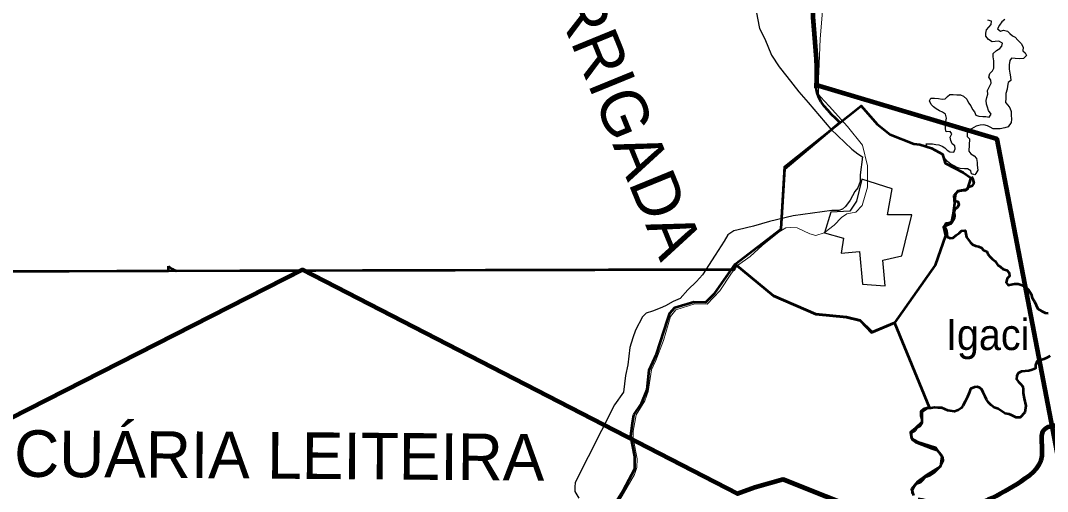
# Model space of a CAD drawing. Extents: x -1643653 to 4543381, y 1624270 to 13878484.
# Drawn here: x 746441 to 762958, y 8940067 to 8947643 of the extents above; entities that cross this region are included whole.
import ezdxf
from ezdxf.enums import TextEntityAlignment as Align

# ---------------------------------------------------------------- set-up
doc = ezdxf.new("R2010")
doc.units = 0
doc.header["$LTSCALE"] = 200
for name, color, linetype, lineweight in [('12', 7, 'Continuous', 25), ('14', 7, 'Continuous', 13), ('17', 7, 'Continuous', 53), ('21', 7, 'Continuous', 25), ('24', 7, 'Continuous', 25), ('26', 7, 'Continuous', 106), ('28', 7, 'Continuous', 53), ('60', 7, 'Continuous', 13), ('9', 7, 'Continuous', 90)]:
    doc.layers.add(name, color=color, linetype=linetype, lineweight=lineweight)
doc.layers.add('41', color=7, linetype='Continuous')
doc.layers.add('42', color=7, linetype='Continuous')

msp = doc.modelspace()

# ---------------------------------------------------------------- linework, layer by layer
at = {"layer": '12'}
for points in [[(758100.6, 8948982.2), (758153.1, 8948438), (758293, 8947683.8), (758328, 8947515.6), (758414, 8947347.3), (758520, 8947087.3), (758641.6, 8946898.6), (758763.3, 8946740.5), (758961.1, 8946495.6), (759108.2, 8946327.2), (759473.4, 8945893.6), (759814, 8945575.9), (759907.3, 8945497.2), (759983.7, 8945452)], [(759983.7, 8945452), (759944.5, 8945159.2), (759944.1, 8945052.2), (759908, 8944950.4), (759862, 8944894.4), (759785, 8944751.9), (759708.2, 8944650.2), (759662.2, 8944609.5), (759602.9, 8944588), (759488.4, 8944585.1)], [(759488.4, 8944585.1), (758867.1, 8944498.9), (758489.8, 8944407.9), (758229.7, 8944337.1), (757985, 8944276.4), (757913.6, 8944261.2), (757816.6, 8944195.2), (757760.2, 8944093.4), (757611.6, 8943869.5), (757411.8, 8943554.1), (757314.6, 8943447.3), (757171.4, 8943310), (757048.7, 8943172.7), (756936.4, 8943121.9), (756813.9, 8943055.9), (756729.6, 8943015), (756604.7, 8942969.7), (756502.7, 8942934.3), (756446.4, 8942878.3), (756333.6, 8942659.5), (756287.3, 8942537.3), (756240.8, 8942384.6), (756209.2, 8942104.5), (756173, 8941931.3), (756141.4, 8941666.5), (755992.9, 8941463), (755361.7, 8940211), (755356.3, 8940134.6), (755356.1, 8940068.4), (755421.9, 8939961.3)]]:
    msp.add_lwpolyline(points, dxfattribs=at)
at = {"layer": '12', "lineweight": 40}
msp.add_spline([(761549.2, 8957020.4), (762383.1, 8955993.9), (763257, 8954902.9), (764214.4, 8953717.3), (766168.2, 8951324.4), (767086.6, 8950171.6), (770317.8, 8946184.2), (771971, 8944146), (773006.3, 8942876.2), (773223.4, 8942642.3), (773373.7, 8942274.8), (774008.3, 8940921.5), (774359, 8940136.3), (774475.8, 8939919.1), (774642.8, 8939785.5), (774893.3, 8939668.5), (775511.2, 8939484.7), (775928.6, 8939267.5), (776078.9, 8939184), (776379.5, 8938916.7), (776680.1, 8938749.6), (776830.4, 8938582.6), (777398.1, 8938348.7), (777899.1, 8938231.7), (778550.4, 8938482.3), (779134.8, 8938866.6), (779452.1, 8939250.8), (779569, 8939384.5), (779685.9, 8939351.1), (779852.9, 8939217.4), (780086.7, 8939217.4), (780604.3, 8939451.3), (781055.2, 8939618.4), (781439.3, 8939618.4), (781823.3, 8939518.1), (782090.5, 8939401.2), (782290.9, 8939367.8), (782524.7, 8939518.1), (782858.7, 8939618.4), (783192.6, 8939651.8), (783509.9, 8939818.9), (783910.7, 8940119.6), (784278.1, 8940336.8), (784625.2, 8940434.5)], degree=3, dxfattribs=at)
at = {"layer": '14'}
for points in [[(756356.5, 8940591.2), (756296.6, 8940917.4), (756291.9, 8941034.6), (756343.8, 8941299.3), (756482.2, 8941523.2), (756533.7, 8941676), (756591, 8942022.3), (756657.8, 8942175), (756781.3, 8942495.7), (756894.8, 8942882.6), (756981.8, 8942989.4), (757287.8, 8943085.7), (757486.4, 8943080.2), (757685.9, 8943293.8), (757875.4, 8943578.7), (757972.7, 8943700.8), (758177, 8943848.1), (758371.2, 8944026.1), (758642, 8944244.6), (758749.2, 8944310.6), (758825.7, 8944315.6), (758932.7, 8944310.3), (759136.1, 8944213.1), (759232.8, 8944182.4), (759365.4, 8944228), (759528.8, 8944349.9), (759646.5, 8944477.1), (759733.3, 8944533), (759876, 8944558.2), (759978.3, 8944665), (760060.9, 8944960.3), (760062.2, 8945306.7), (759981.9, 8945637.9), (759743.6, 8945938.9), (759444.2, 8946265.5), (759307.2, 8946418.6), (759276.8, 8946459.4), (759277.1, 8946556.2), (759272.6, 8946703.9), (759283.7, 8946948.4), (759300.4, 8947350.8), (759434.4, 8948959.2)], [(756079, 8939934.6), (756314.8, 8940341.7), (756356, 8940453.7), (756356.5, 8940591.2)]]:
    msp.add_lwpolyline(points, dxfattribs=at)
at = {"layer": '17'}
msp.add_lwpolyline([(760138.8, 8942630.4), (759944.6, 8942815.9), (759724, 8942868.9), (759229.7, 8942921.8), (758550.1, 8943213.2), (757932.3, 8943725.4), (758673.7, 8944290.6), (758735.5, 8945297.2), (759962.3, 8946268.6), (760216.8, 8945977.6), (760428.7, 8945809.8), (760808.2, 8945659.7), (760905.3, 8945650.9), (761090.6, 8945589.1), (761267.1, 8945491.9), (761311.2, 8945350.6), (761602.5, 8945200.5), (761726.1, 8945112.2), (761664.3, 8944926.8), (761514.2, 8944900.3), (761452.5, 8944820.8), (761461.3, 8944697.2), (761443.6, 8944538.2), (761408.3, 8944379.3), (761284.8, 8944326.3), (761320.1, 8944185), (761152.4, 8943708.2), (760499.3, 8942781)], close=True, dxfattribs=at)
at = {"layer": '21'}
msp.add_lwpolyline([(759971.8, 8945092.7), (759884.4, 8944737), (759777.9, 8944573.9), (759473.6, 8944557.9), (759374.4, 8944228.2), (759675.4, 8944141.8), (759642.3, 8943899.6), (759934.4, 8943928.7), (759980.7, 8943402.3), (760347, 8943377.8), (760309.6, 8943788.8), (760615.6, 8943855.9), (760776.1, 8944516.6), (760383.6, 8944516.3), (760460.4, 8944936.4)], close=True, dxfattribs=at)
at = {"layer": '24'}
for points in [[(762274, 8947657.5), (762222.9, 8947622.2), (762186.9, 8947571.5), (762156, 8947510.5), (762201.5, 8947474.6), (762252.5, 8947489.6), (762313.4, 8947473.9), (762353.8, 8947432.9), (762394.3, 8947396.9), (762439.9, 8947376.3), (762480.3, 8947330.2), (762535.8, 8947273.8), (762565.9, 8947212.5), (762560.5, 8947156.5), (762600.9, 8947125.7), (762621, 8947079.7), (762569.8, 8947034.2), (762508.7, 8947029.5), (762437.6, 8947035), (762381.7, 8947040.5), (762350.9, 8946999.9), (762340.2, 8946928.7), (762339.7, 8946862.4), (762354.5, 8946796.1), (762364.3, 8946740), (762369, 8946678.9), (762328.1, 8946648.6), (762312.4, 8946587.6), (762307, 8946536.7), (762286.2, 8946470.6), (762285.7, 8946394.2), (762285.2, 8946322.8), (762320.5, 8946281.9), (762350.7, 8946240.9), (762375.7, 8946179.6), (762375.3, 8946123.6), (762380, 8946057.4), (762374.5, 8946001.4), (762328.3, 8945935.4), (762272.2, 8945915.4), (762195.8, 8945900.6), (762134.8, 8945901), (762083.9, 8945901.3), (762038.3, 8945927.1), (761992.7, 8945947.8), (761931.8, 8945963.4), (761875.8, 8945958.7), (761809.6, 8945943.9), (761738.1, 8945903.6), (761682, 8945883.6), (761666.4, 8945832.7), (761666, 8945776.7), (761706.4, 8945740.8), (761694.9, 8945542.2), (761725.1, 8945501.2), (761781.5, 8945468.3), (761814.4, 8945424.2), (761825.4, 8945358.2), (761825.4, 8945314.1), (761836.4, 8945237.1), (761803.4, 8945182), (761788.9, 8945159.5), (761738.1, 8945175.1), (761723.2, 8945226.2), (761672.6, 8945257.1), (761621.7, 8945257.4), (761555.6, 8945262.9), (761504.9, 8945278.5), (761459.3, 8945304.3), (761403.6, 8945335.2), (761347.9, 8945376.3), (761312.6, 8945417.3), (761292.5, 8945463.3), (761247.1, 8945509.4), (761176.1, 8945540.4), (761125.4, 8945561.1), (761069.6, 8945586.9), (761024, 8945607.6), (761009.1, 8945658.6), (761059.9, 8945658.3), (761110.8, 8945658), (761161.6, 8945647.5), (761212.4, 8945642.1), (761263.1, 8945621.4), (761308.7, 8945595.6), (761344.1, 8945559.7), (761389.6, 8945528.9)], [(761389.6, 8945528.9), (761450.6, 8945523.4), (761471.3, 8945579.3), (761466.6, 8945630.2), (761426.1, 8945661.1), (761401.1, 8945712.2), (761391.3, 8945768.3), (761422.1, 8945819), (761391.9, 8945859.9), (761330.8, 8945850.2), (761315.9, 8945901.2), (761316.3, 8945967.4), (761321.8, 8946018.3), (761332.3, 8946074.3), (761317.5, 8946135.5), (761272, 8946171.4), (761221.3, 8946192.1), (761165.5, 8946223.1), (761125, 8946253.9), (761089.7, 8946294.9), (761059.6, 8946351.1), (761080.2, 8946396.8), (761141.3, 8946396.4), (761207.4, 8946390.9), (761263.2, 8946380.3), (761314.1, 8946385.1), (761350, 8946420.5), (761385.8, 8946456), (761441.8, 8946455.6), (761497.7, 8946450.2), (761558.7, 8946449.8), (761609.4, 8946429.1), (761659.9, 8946377.8), (761690.1, 8946321.6), (761725.3, 8946270.4), (761750.4, 8946214.2), (761785.7, 8946173.2), (761805.7, 8946122.2), (761856.4, 8946106.6), (761917.4, 8946101.1), (761968.3, 8946100.8), (762019.1, 8946090.2), (762055, 8946135.8), (762009.7, 8946197.3), (761994.7, 8946248.3), (761974.8, 8946299.4), (761970.1, 8946355.4), (761980.6, 8946406.3), (761996.2, 8946457.1), (761991.5, 8946518.3), (762022.4, 8946574.1), (762053.3, 8946635.1), (762048.6, 8946686), (762013.3, 8946732.1), (762029, 8946793.1), (762075.1, 8946833.6), (762095.7, 8946879.3), (762096.2, 8946945.5), (762096.5, 8946996.4), (762086.8, 8947057.6), (762082.1, 8947113.7), (762138.3, 8947159.2), (762189.4, 8947194.5), (762225.3, 8947229.9), (762235.8, 8947280.8), (762175, 8947311.8), (762119, 8947307), (762068.1, 8947302.3), (762007.3, 8947338.3), (761967, 8947389.5), (761967.3, 8947440.4), (761977.9, 8947491.3), (762013.8, 8947536.9), (762049.7, 8947577.4), (762060.2, 8947633.4), (761999.3, 8947649.1)]]:
    msp.add_lwpolyline(points, dxfattribs=at)
at = {"layer": '24', "lineweight": 53}
for points in [[(761737.3, 8945134.7), (761755.2, 8945087.5), (761775.2, 8945026.3), (761739.2, 8944980.7), (761683.1, 8944955.6), (761637, 8944910), (761576, 8944905.3), (761514.8, 8944890.4), (761479, 8944855), (761468.4, 8944799), (761468, 8944743), (761518.8, 8944732.5), (761533.7, 8944681.5), (761513.1, 8944635.7), (761467.1, 8944610.6), (761451.5, 8944559.7), (761461.3, 8944508.7), (761455.9, 8944457.8), (761425, 8944407.1), (761374, 8944381.9), (761323.1, 8944377.2), (761302.4, 8944331.5), (761327.5, 8944275.3), (761337.3, 8944219.2), (761347.1, 8944163.1), (761392.7, 8944142.4), (761443.6, 8944147.2), (761489.7, 8944192.7), (761535.7, 8944223), (761576.6, 8944258.4), (761632.6, 8944263.1), (761642.4, 8944212.1), (761657.3, 8944156), (761687.5, 8944115.1), (761717.7, 8944074.1), (761753.1, 8944038.2), (761798.7, 8944017.6), (761849.5, 8944007), (761895.2, 8943986.4), (761930.5, 8943950.5), (761981.2, 8943929.8), (762001.3, 8943883.8), (762036.6, 8943842.8), (762071.9, 8943801.9), (762117.5, 8943771), (762157.7, 8943709.6), (762203.3, 8943678.8), (762243.7, 8943642.8), (762304.7, 8943627.2), (762340, 8943586.2), (762349.8, 8943530.1), (762308.8, 8943494.7), (762293.1, 8943428.6), (762323.4, 8943387.7), (762374.3, 8943397.5), (762425.2, 8943407.4), (762486.2, 8943407), (762552.2, 8943386.2), (762613, 8943350.1), (762653.4, 8943309.1), (762693.7, 8943242.6), (762713.6, 8943181.4), (762748.8, 8943125.1), (762773.8, 8943063.8), (762803.9, 8943007.6)], [(762803.9, 8943007.6), (762864.7, 8942966.5), (762920.5, 8942940.7), (762971.3, 8942935.2)], [(763002.2, 8942247.4), (762946, 8942217.2), (762900.1, 8942197.1), (762849.1, 8942177), (762787.9, 8942157.1), (762767.2, 8942101.2), (762766.8, 8942045.1), (762710.7, 8942025.1), (762659.8, 8942010.2), (762598.7, 8942000.3), (762537.6, 8941995.7), (762486.6, 8941970.5), (762465.9, 8941924.8), (762460.5, 8941873.9), (762490.7, 8941832.9), (762526.1, 8941797.1), (762561.4, 8941756.1), (762566.1, 8941705.1), (762565.7, 8941649.1)], [(762565.7, 8941649.1), (762580.6, 8941564.2), (762580.6, 8941564.2), (762611.1, 8941442.4), (762595.8, 8941335.7), (762519.6, 8941259.6), (762453.6, 8941259.6), (762377.4, 8941292.5), (762340.6, 8941308.9), (762279.2, 8941321.2), (762230.1, 8941353.9), (762164.6, 8941394.8), (762103.2, 8941419.3), (762051.3, 8941456.8), (762010.3, 8941499.8), (761975, 8941545.9), (761955, 8941597), (761924.9, 8941658.3), (761899.8, 8941709.4), (761871.3, 8941731.8), (761831, 8941748.4), (761783.1, 8941745.8), (761721.9, 8941715.6), (761696, 8941655.9), (761672.3, 8941589.5), (761634.4, 8941513.7), (761596.5, 8941447.3), (761568.1, 8941409.3), (761520.8, 8941376.1), (761463.9, 8941352.4), (761392.8, 8941366.6), (761355, 8941371.4), (761307.6, 8941390.3), (761257, 8941413), (761201, 8941413.3), (761140, 8941418.8), (761080.2, 8941404.6), (761018.6, 8941409.3), (760966.5, 8941390.3), (760919.1, 8941352.4), (760920.8, 8941343.8), (760920.4, 8941282.7), (760935.3, 8941231.7), (760934.8, 8941165.4), (760904, 8941119.8), (760852.9, 8941089.6), (760830.3, 8941047.1), (760764.8, 8941010.3), (760764.8, 8941010.3), (760764.8, 8940957.1), (760780.4, 8940901.6), (760841.2, 8940860.4), (761104.9, 8940756.8), (761184.4, 8940731.1), (761241.3, 8940660), (761269.7, 8940617.3), (761272.5, 8940557.8), (761245.1, 8940495.9), (761203.9, 8940441), (761135.3, 8940372.3), (761059.8, 8940324.2), (761025.5, 8940310.4), (760989.9, 8940299.1), (760943.7, 8940243.4), (760902.8, 8940208)], [(760902.8, 8940208), (760846.7, 8940188), (760810.8, 8940142.4), (760779.9, 8940086.5), (760779.6, 8940035.6)]]:
    msp.add_lwpolyline(points, dxfattribs=at)
at = {"layer": '26'}
msp.add_lwpolyline([(737637.3, 8917498.1), (741487, 8913799.2), (751263.9, 8913799.2), (755491.7, 8914698), (756495.8, 8917341.8), (762467.6, 8919403.9), (760776.5, 8922153.4), (765744.2, 8926965), (762150.6, 8945735.5), (759238.1, 8946605.9)], dxfattribs=at)
msp.add_spline([(738865.3, 8967422.1), (739557.2, 8967298.3), (740701.8, 8967013.8), (741413.3, 8966731.2), (743000.3, 8965872.6), (743559.1, 8965590.5), (744439.9, 8965968.4), (745374, 8966727.6), (746233.2, 8967779.5), (746809, 8968247.7), (747844.5, 8968942.9), (749056.2, 8969268.5), (750229.7, 8969581.6), (752050.8, 8969574.1), (752518.4, 8968949.1), (753046.2, 8967700.6), (754351.7, 8964009.2), (754013.3, 8962799.9), (754158.3, 8961590.6), (754279.2, 8959994.3), (754448.4, 8958857.5), (755069.1, 8957779.3), (755600.9, 8957368.1), (756072.3, 8957077.8), (756075.9, 8956332), (756399.8, 8955071.7), (756665.8, 8954671.3), (757824.9, 8954152.2), (758684.7, 8953765.2), (759807.2, 8953486.2), (759964.3, 8952494.5), (759785.3, 8951475.9), (759658.7, 8951007.7), (759460.5, 8950660.7), (759411.1, 8950095.7), (759130.3, 8949726.7), (759168.8, 8949567), (759377.9, 8949449), (759532.1, 8949168), (759383.5, 8948839.9), (759243.4, 8946764.2), (759236.6, 8946560.6)], degree=3, dxfattribs=at)
at = {"layer": '28'}
for points in [[(748941.6, 8943614.3), (757924.1, 8943639.7), (757932.3, 8943725.4), (758673.7, 8944290.6), (758733.2, 8945259.8), (759620.3, 8946005.2)], [(743700.5, 8944897.8), (744028.3, 8943600.4), (748822.6, 8943613.9), (748822.4, 8943694.2)], [(756023.5, 8939897.8), (756140.1, 8940090.3), (756320.9, 8940428.6), (756320.3, 8940628.8), (756256.1, 8940961.3), (756285.3, 8941165.5), (756302.8, 8941299.7), (756431.1, 8941480.5), (756518.5, 8941708), (756553.5, 8942017.2), (756670.1, 8942273.9), (756850.6, 8942837.9), (756885.6, 8942937.1), (756967.2, 8943024.6), (757270.4, 8943117.9), (757462.8, 8943112.1), (757608.6, 8943257.9), (757758.2, 8943470.2), (757932.3, 8943725.4), (758550.1, 8943213.2), (759229.7, 8942921.8), (759724, 8942868.9), (759944.6, 8942815.9), (760126.3, 8942622.6), (760499.3, 8942781), (761052.7, 8941423.4), (760936.1, 8941341.7), (760936.1, 8941184.2), (760837, 8941085), (760755.3, 8941020.8), (760772.8, 8940921.7), (760866.1, 8940863.3), (761157.7, 8940775.8), (761256.8, 8940624.1), (761239.3, 8940466.6), (761011.9, 8940326.6), (760866.1, 8940221.6), (760772.8, 8940104.9), (760802, 8939999.9)], [(756023.5, 8939897.8), (756140.1, 8940090.3), (756320.9, 8940428.6), (756320.3, 8940628.8), (756256.1, 8940961.3), (756285.3, 8941165.5), (756302.8, 8941299.7), (756431.1, 8941480.5), (756518.5, 8941708), (756553.5, 8942017.2), (756670.1, 8942273.9), (756850.6, 8942837.9), (756885.6, 8942937.1), (756967.2, 8943024.6), (757270.4, 8943117.9), (757462.8, 8943112.1), (757608.6, 8943257.9), (757758.2, 8943470.2), (757873.8, 8943639.6), (744028.3, 8943600.4)]]:
    msp.add_lwpolyline(points, dxfattribs=at)
msp.add_spline([(759620.3, 8946005.2), (759236.6, 8946560.6), (759243.4, 8946764.2), (759383.5, 8948839.9), (759532.1, 8949168), (759377.9, 8949449), (759168.8, 8949567), (759130.3, 8949726.7), (759411.1, 8950095.7), (759460.5, 8950660.7), (759658.7, 8951007.7), (759785.3, 8951475.9), (759976.4, 8952615.4), (759698.4, 8953607.1), (758684.7, 8953765.2), (758151.3, 8954018.2)], degree=3, dxfattribs=at)
msp.add_open_spline([(748822.4, 8943694.2), (748856, 8943659.8), (748896.5, 8943634.1), (748941.6, 8943614.3)], degree=3, dxfattribs=at)
at = {"layer": '60', "lineweight": 25}
msp.add_spline([(814781, 9009175.5), (814787.2, 9009173.4), (814796.9, 9009173.4), (814799.4, 9009172.4), (814805.1, 9009174.5), (814805.6, 9009176.5), (814811.7, 9009179.5), (814811.7, 9009179.5), (814801.5, 9009181), (814790.7, 9009181.5), (814784.1, 9009183.1), (814777.4, 9009185.1), (814778.4, 9009175.5)], degree=3, dxfattribs=at)
at = {"layer": '9'}
msp.add_lwpolyline([(760739.9, 8939450.1), (758705.7, 8940260.8), (758249.4, 8940131.7), (757970.6, 8940028.8), (750978.7, 8943631.9), (743914.7, 8940037.6)], dxfattribs=at)
msp.add_lwpolyline([(760739.9, 8939450.1), (758705.7, 8940260.8), (758249.4, 8940131.7), (757970.6, 8940028.8), (750978.7, 8943631.9), (743914.7, 8940037.6)], dxfattribs=at)
msp.add_spline([(779358.3, 8951316.5), (778152, 8950383.2), (776870.5, 8948893), (775858.2, 8948102.8), (775096.9, 8948098.3), (774081.6, 8948143.1), (772814, 8947781.5), (772105.2, 8947296.6), (771547.4, 8947166.9), (771322, 8946330.6), (771374.4, 8945875.5), (771395.1, 8945546.1), (769593.3, 8944681.6), (768541.6, 8943918.8), (767488.3, 8942812.2), (766189.2, 8941452.3), (765366.7, 8940769), (764084.5, 8940646.2), (763321.5, 8941097.2), (762890.2, 8941044.2), (762866.3, 8940639.2), (762461.9, 8940181.4), (761397.4, 8939821), (760940.2, 8939919.5), (760875, 8939930.2)], degree=3, dxfattribs=at)

# ---------------------------------------------------------------- texts
at = {"layer": '41', "width": 0.95}
msp.add_text('Igaci', height=500, dxfattribs=at).set_placement((761325, 8942341.6))
at = {"layer": '42'}
for s, rotation, p in [('FRUTICULTURA E FORRAGEIRA (BOVINOS) IRRIGADA', 292.237, (751782.1, 8955862.9)), ('PECUÁRIA LEITEIRA', 359.575, (749931.5, 8940277.1))]:
    msp.add_text(s, height=750, rotation=rotation, dxfattribs=at).set_placement(p, align=Align.CENTER)

doc.saveas('drawing.dxf')
